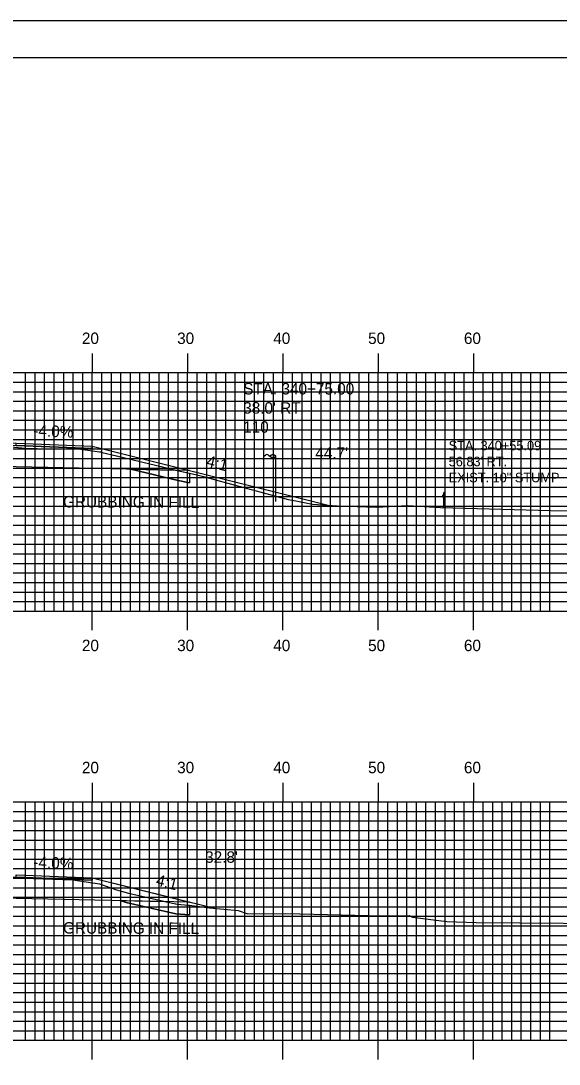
# Model space of a CAD drawing. Extents: x 1824360 to 1824703, y 442591 to 442811.
# Drawn here: x 1824537.8 to 1824594.3, y 442701.2 to 442810.5 of the extents above; entities that cross this region are included whole.
import ezdxf

# ---------------------------------------------------------------- set-up
doc = ezdxf.new("R2010")
doc.units = 0
for name, color, linetype in [('ANNOTATION', 7, 'Continuous'), ('BORDER', 7, 'Continuous'), ('D_Drainage_Text', 7, 'Continuous'), ('D_Roadway_Centerline', 7, 'Continuous'), ('D_Roadway_Edge_Shoulder', 7, 'Continuous'), ('D_Roadway_SlopeLines', 7, 'Continuous'), ('D_Roadway_SubGrade', 7, 'Continuous'), ('D_Text_Monospaced', 7, 'Continuous'), ('D_Text_Standard', 7, 'Continuous'), ('D_Utilities_Pole_Joint', 7, 'Continuous'), ('GRUBBING IN FILL', 7, 'Continuous'), ('H_V ANNOTATION', 7, 'Continuous'), ('MAJOR', 7, 'Continuous'), ('MINOR', 7, 'Continuous'), ('PLOT BOUNDARY', 7, 'Continuous'), ('S_Roadway_Centerline', 7, 'Continuous'), ('S_Trees_Dead_NonPay', 7, 'Continuous')]:
    doc.layers.add(name, color=color, linetype=linetype)

msp = doc.modelspace()

# ---------------------------------------------------------------- linework, layer by layer
at = {"layer": 'BORDER'}
msp.add_lwpolyline([(1824375.73, 442596.67), (1824695.73, 442596.67), (1824695.73, 442806.67), (1824375.73, 442806.67)], close=True, dxfattribs=at)
at = {"layer": 'D_Roadway_Centerline'}
msp.add_lwpolyline([(1824477.1, 442758.9), (1824495.16, 442763.42), (1824505.33, 442765.96), (1824513.33, 442766.28), (1824525.33, 442766.52), (1824537.33, 442766.28), (1824545.33, 442765.96), (1824555.51, 442763.42), (1824570.07, 442759.78)], dxfattribs=at)
at = {"layer": 'D_Roadway_Edge_Shoulder'}
for points in [[(1824537.33, 442766.28), (1824545.33, 442765.96), (1824545.33, 442765.71), (1824537.33, 442766.03)], [(1824537.33, 442721.03), (1824545.33, 442720.71), (1824545.33, 442720.46), (1824537.33, 442720.78)]]:
    msp.add_lwpolyline(points, close=True, dxfattribs=at)
at = {"layer": 'D_Roadway_SlopeLines'}
for points in [[(1824545.33, 442765.96), (1824555.51, 442763.42), (1824570.07, 442759.78)], [(1824545.33, 442720.71), (1824558.13, 442717.51)]]:
    msp.add_lwpolyline(points, dxfattribs=at)
at = {"layer": 'D_Roadway_SubGrade'}
for points in [[(1824513.33, 442763.78), (1824495.16, 442763.42), (1824505.33, 442765.96), (1824505.33, 442765.71), (1824513.33, 442766.03), (1824525.33, 442766.27), (1824537.33, 442766.03), (1824545.33, 442765.71), (1824545.33, 442765.96), (1824555.51, 442763.42), (1824537.33, 442763.78), (1824525.33, 442764.02)], [(1824513.33, 442718.53), (1824495.16, 442718.17), (1824505.33, 442720.71), (1824505.33, 442720.46), (1824513.33, 442720.78), (1824525.33, 442721.02), (1824537.33, 442720.78), (1824545.33, 442720.46), (1824545.33, 442720.71), (1824555.51, 442718.17), (1824537.33, 442718.53), (1824525.33, 442718.77)]]:
    msp.add_lwpolyline(points, close=True, dxfattribs=at)
at = {"layer": 'D_Utilities_Pole_Joint'}
for p, q in [((1824563.33, 442764.92), (1824563.49, 442765.03)), ((1824563.33, 442760.16), (1824563.33, 442764.92)), ((1824563.8, 442765.03), (1824563.96, 442764.92)), ((1824564.12, 442765.03), (1824563.96, 442764.92)), ((1824563.96, 442764.92), (1824564.12, 442764.8)), ((1824564.58, 442764.92), (1824564.43, 442765.03)), ((1824564.43, 442764.8), (1824564.58, 442764.92)), ((1824564.58, 442760.16), (1824564.58, 442764.92))]:
    msp.add_line(p, q, dxfattribs=at)
for centre, start, end in [((1824563.65, 442764.8), 90, 125.2644), ((1824563.65, 442764.8), 54.7356, 90), ((1824564.27, 442764.8), 90, 125.2644), ((1824564.27, 442765.03), 234.7356, 270), ((1824564.27, 442764.8), 54.7356, 90), ((1824564.27, 442765.03), 270, 305.2644)]:
    msp.add_arc(centre, 0.271, start, end, dxfattribs=at)
at = {"layer": 'GRUBBING IN FILL'}
for p, q in [((1824555.51, 442763.12), (1824555.51, 442762.1)), ((1824555.51, 442763.12), (1824555.51, 442762.1)), ((1824555.51, 442717.83), (1824555.51, 442716.83)), ((1824555.51, 442717.83), (1824555.51, 442716.83))]:
    msp.add_line(p, q, dxfattribs=at)
for points in [[(1824549.38, 442763.54), (1824554.35, 442762.35), (1824555.51, 442762.1)], [(1824549.38, 442763.54), (1824554.35, 442762.35), (1824555.51, 442762.1)], [(1824548.2, 442718.32), (1824548.87, 442718.13), (1824554.09, 442716.93), (1824555.51, 442716.83)], [(1824548.2, 442718.32), (1824548.87, 442718.13), (1824554.09, 442716.93), (1824555.51, 442716.83)]]:
    msp.add_lwpolyline(points, dxfattribs=at)
for points in [[(1824549.38, 442763.54), (1824554.06, 442763.45), (1824555.51, 442763.12), (1824555.51, 442762.1), (1824554.35, 442762.35), (1824551.86, 442762.95)], [(1824549.38, 442763.54), (1824554.06, 442763.45), (1824555.51, 442763.12), (1824555.51, 442762.1), (1824554.35, 442762.35), (1824551.86, 442762.95)], [(1824548.2, 442718.32), (1824552.95, 442718.22), (1824554.24, 442717.93), (1824555.01, 442717.87), (1824555.51, 442717.83), (1824555.51, 442716.83), (1824554.09, 442716.93), (1824551.48, 442717.53), (1824548.87, 442718.13)], [(1824548.2, 442718.32), (1824552.95, 442718.22), (1824554.24, 442717.93), (1824555.01, 442717.87), (1824555.51, 442717.83), (1824555.51, 442716.83), (1824554.09, 442716.93), (1824551.48, 442717.53), (1824548.87, 442718.13)]]:
    msp.add_lwpolyline(points, close=True, dxfattribs=at)
at = {"layer": 'MAJOR'}
for p, q in [((1824545.33, 442775.67), (1824545.33, 442773.67)), ((1824555.33, 442775.67), (1824555.33, 442773.67)), ((1824565.33, 442775.67), (1824565.33, 442773.67)), ((1824575.33, 442775.67), (1824575.33, 442773.67)), ((1824585.33, 442775.67), (1824585.33, 442773.67)), ((1824385.33, 442773.67), (1824665.33, 442773.67)), ((1824385.33, 442773.67), (1824665.33, 442773.67)), ((1824545.33, 442748.67), (1824545.33, 442773.67)), ((1824555.33, 442748.67), (1824555.33, 442773.67)), ((1824565.33, 442748.67), (1824565.33, 442773.67)), ((1824575.33, 442748.67), (1824575.33, 442773.67)), ((1824585.33, 442748.67), (1824585.33, 442773.67)), ((1824385.33, 442768.67), (1824665.33, 442768.67)), ((1824385.33, 442763.67), (1824665.33, 442763.67)), ((1824385.33, 442758.67), (1824665.33, 442758.67)), ((1824385.33, 442753.67), (1824665.33, 442753.67)), ((1824385.33, 442748.67), (1824665.33, 442748.67)), ((1824385.33, 442748.67), (1824665.33, 442748.67)), ((1824545.33, 442746.66), (1824545.33, 442748.67)), ((1824555.33, 442746.66), (1824555.33, 442748.67)), ((1824565.33, 442746.66), (1824565.33, 442748.67)), ((1824575.33, 442746.66), (1824575.33, 442748.67)), ((1824585.33, 442746.66), (1824585.33, 442748.67)), ((1824545.33, 442730.67), (1824545.33, 442728.67)), ((1824555.33, 442730.67), (1824555.33, 442728.67)), ((1824565.33, 442730.67), (1824565.33, 442728.67)), ((1824575.33, 442730.67), (1824575.33, 442728.67)), ((1824585.33, 442730.67), (1824585.33, 442728.67)), ((1824385.33, 442728.67), (1824665.33, 442728.67)), ((1824385.33, 442728.67), (1824665.33, 442728.67)), ((1824545.33, 442703.67), (1824545.33, 442728.67)), ((1824555.33, 442703.67), (1824555.33, 442728.67)), ((1824565.33, 442703.67), (1824565.33, 442728.67)), ((1824575.33, 442703.67), (1824575.33, 442728.67)), ((1824585.33, 442703.67), (1824585.33, 442728.67)), ((1824385.33, 442723.67), (1824665.33, 442723.67)), ((1824385.33, 442718.67), (1824665.33, 442718.67)), ((1824385.33, 442713.67), (1824665.33, 442713.67)), ((1824385.33, 442708.67), (1824665.33, 442708.67)), ((1824385.33, 442703.67), (1824665.33, 442703.67)), ((1824385.33, 442703.67), (1824665.33, 442703.67)), ((1824545.33, 442701.66), (1824545.33, 442703.67)), ((1824555.33, 442701.66), (1824555.33, 442703.67)), ((1824565.33, 442701.66), (1824565.33, 442703.67)), ((1824575.33, 442701.66), (1824575.33, 442703.67)), ((1824585.33, 442701.66), (1824585.33, 442703.67))]:
    msp.add_line(p, q, dxfattribs=at)
at = {"layer": 'MINOR'}
for p, q in [((1824538.33, 442748.67), (1824538.33, 442773.67)), ((1824539.33, 442748.67), (1824539.33, 442773.67)), ((1824540.33, 442748.67), (1824540.33, 442773.67)), ((1824541.33, 442748.67), (1824541.33, 442773.67)), ((1824542.33, 442748.67), (1824542.33, 442773.67)), ((1824543.33, 442748.67), (1824543.33, 442773.67)), ((1824544.33, 442748.67), (1824544.33, 442773.67)), ((1824546.33, 442748.67), (1824546.33, 442773.67)), ((1824547.33, 442748.67), (1824547.33, 442773.67)), ((1824548.33, 442748.67), (1824548.33, 442773.67)), ((1824549.33, 442748.67), (1824549.33, 442773.67)), ((1824550.33, 442748.67), (1824550.33, 442773.67)), ((1824551.33, 442748.67), (1824551.33, 442773.67)), ((1824552.33, 442748.67), (1824552.33, 442773.67)), ((1824553.33, 442748.67), (1824553.33, 442773.67)), ((1824554.33, 442748.67), (1824554.33, 442773.67)), ((1824556.33, 442748.67), (1824556.33, 442773.67)), ((1824557.33, 442748.67), (1824557.33, 442773.67)), ((1824558.33, 442748.67), (1824558.33, 442773.67)), ((1824559.33, 442748.67), (1824559.33, 442773.67)), ((1824560.33, 442748.67), (1824560.33, 442773.67)), ((1824561.33, 442748.67), (1824561.33, 442773.67)), ((1824562.33, 442748.67), (1824562.33, 442773.67)), ((1824563.33, 442748.67), (1824563.33, 442773.67)), ((1824564.33, 442748.67), (1824564.33, 442773.67)), ((1824566.33, 442748.67), (1824566.33, 442773.67)), ((1824567.33, 442748.67), (1824567.33, 442773.67)), ((1824568.33, 442748.67), (1824568.33, 442773.67)), ((1824569.33, 442748.67), (1824569.33, 442773.67)), ((1824570.33, 442748.67), (1824570.33, 442773.67)), ((1824571.33, 442748.67), (1824571.33, 442773.67)), ((1824572.33, 442748.67), (1824572.33, 442773.67)), ((1824573.33, 442748.67), (1824573.33, 442773.67)), ((1824574.33, 442748.67), (1824574.33, 442773.67)), ((1824576.33, 442748.67), (1824576.33, 442773.67)), ((1824577.33, 442748.67), (1824577.33, 442773.67)), ((1824578.33, 442748.67), (1824578.33, 442773.67)), ((1824579.33, 442748.67), (1824579.33, 442773.67)), ((1824580.33, 442748.67), (1824580.33, 442773.67)), ((1824581.33, 442748.67), (1824581.33, 442773.67)), ((1824582.33, 442748.67), (1824582.33, 442773.67)), ((1824583.33, 442748.67), (1824583.33, 442773.67)), ((1824584.33, 442748.67), (1824584.33, 442773.67)), ((1824586.33, 442748.67), (1824586.33, 442773.67)), ((1824587.33, 442748.67), (1824587.33, 442773.67)), ((1824588.33, 442748.67), (1824588.33, 442773.67)), ((1824589.33, 442748.67), (1824589.33, 442773.67)), ((1824590.33, 442748.67), (1824590.33, 442773.67)), ((1824591.33, 442748.67), (1824591.33, 442773.67)), ((1824592.33, 442748.67), (1824592.33, 442773.67)), ((1824593.33, 442748.67), (1824593.33, 442773.67)), ((1824385.33, 442772.67), (1824665.33, 442772.67)), ((1824385.33, 442771.67), (1824665.33, 442771.67)), ((1824385.33, 442770.67), (1824665.33, 442770.67)), ((1824385.33, 442769.67), (1824665.33, 442769.67)), ((1824385.33, 442767.67), (1824665.33, 442767.67)), ((1824385.33, 442766.67), (1824665.33, 442766.67)), ((1824385.33, 442765.67), (1824665.33, 442765.67)), ((1824385.33, 442764.67), (1824665.33, 442764.67)), ((1824385.33, 442762.67), (1824665.33, 442762.67)), ((1824385.33, 442761.67), (1824665.33, 442761.67)), ((1824385.33, 442760.67), (1824665.33, 442760.67)), ((1824385.33, 442759.67), (1824665.33, 442759.67)), ((1824385.33, 442757.67), (1824665.33, 442757.67)), ((1824385.33, 442756.67), (1824665.33, 442756.67)), ((1824385.33, 442755.67), (1824665.33, 442755.67)), ((1824385.33, 442754.67), (1824665.33, 442754.67)), ((1824385.33, 442752.67), (1824665.33, 442752.67)), ((1824385.33, 442751.67), (1824665.33, 442751.67)), ((1824385.33, 442750.67), (1824665.33, 442750.67)), ((1824385.33, 442749.67), (1824665.33, 442749.67)), ((1824538.33, 442703.67), (1824538.33, 442728.67)), ((1824539.33, 442703.67), (1824539.33, 442728.67)), ((1824540.33, 442703.67), (1824540.33, 442728.67)), ((1824541.33, 442703.67), (1824541.33, 442728.67)), ((1824542.33, 442703.67), (1824542.33, 442728.67)), ((1824543.33, 442703.67), (1824543.33, 442728.67)), ((1824544.33, 442703.67), (1824544.33, 442728.67)), ((1824546.33, 442703.67), (1824546.33, 442728.67)), ((1824547.33, 442703.67), (1824547.33, 442728.67)), ((1824548.33, 442703.67), (1824548.33, 442728.67)), ((1824549.33, 442703.67), (1824549.33, 442728.67)), ((1824550.33, 442703.67), (1824550.33, 442728.67)), ((1824551.33, 442703.67), (1824551.33, 442728.67)), ((1824552.33, 442703.67), (1824552.33, 442728.67)), ((1824553.33, 442703.67), (1824553.33, 442728.67)), ((1824554.33, 442703.67), (1824554.33, 442728.67)), ((1824556.33, 442703.67), (1824556.33, 442728.67)), ((1824557.33, 442703.67), (1824557.33, 442728.67)), ((1824558.33, 442703.67), (1824558.33, 442728.67)), ((1824559.33, 442703.67), (1824559.33, 442728.67)), ((1824560.33, 442703.67), (1824560.33, 442728.67)), ((1824561.33, 442703.67), (1824561.33, 442728.67)), ((1824562.33, 442703.67), (1824562.33, 442728.67)), ((1824563.33, 442703.67), (1824563.33, 442728.67)), ((1824564.33, 442703.67), (1824564.33, 442728.67)), ((1824566.33, 442703.67), (1824566.33, 442728.67)), ((1824567.33, 442703.67), (1824567.33, 442728.67)), ((1824568.33, 442703.67), (1824568.33, 442728.67)), ((1824569.33, 442703.67), (1824569.33, 442728.67)), ((1824570.33, 442703.67), (1824570.33, 442728.67)), ((1824571.33, 442703.67), (1824571.33, 442728.67)), ((1824572.33, 442703.67), (1824572.33, 442728.67)), ((1824573.33, 442703.67), (1824573.33, 442728.67)), ((1824574.33, 442703.67), (1824574.33, 442728.67)), ((1824576.33, 442703.67), (1824576.33, 442728.67)), ((1824577.33, 442703.67), (1824577.33, 442728.67)), ((1824578.33, 442703.67), (1824578.33, 442728.67)), ((1824579.33, 442703.67), (1824579.33, 442728.67)), ((1824580.33, 442703.67), (1824580.33, 442728.67)), ((1824581.33, 442703.67), (1824581.33, 442728.67)), ((1824582.33, 442703.67), (1824582.33, 442728.67)), ((1824583.33, 442703.67), (1824583.33, 442728.67)), ((1824584.33, 442703.67), (1824584.33, 442728.67)), ((1824586.33, 442703.67), (1824586.33, 442728.67)), ((1824587.33, 442703.67), (1824587.33, 442728.67)), ((1824588.33, 442703.67), (1824588.33, 442728.67)), ((1824589.33, 442703.67), (1824589.33, 442728.67)), ((1824590.33, 442703.67), (1824590.33, 442728.67)), ((1824591.33, 442703.67), (1824591.33, 442728.67)), ((1824592.33, 442703.67), (1824592.33, 442728.67)), ((1824593.33, 442703.67), (1824593.33, 442728.67)), ((1824385.33, 442727.67), (1824665.33, 442727.67)), ((1824385.33, 442726.67), (1824665.33, 442726.67)), ((1824385.33, 442725.67), (1824665.33, 442725.67)), ((1824385.33, 442724.67), (1824665.33, 442724.67)), ((1824385.33, 442722.67), (1824665.33, 442722.67)), ((1824385.33, 442721.67), (1824665.33, 442721.67)), ((1824385.33, 442720.67), (1824665.33, 442720.67)), ((1824385.33, 442719.67), (1824665.33, 442719.67)), ((1824385.33, 442717.67), (1824665.33, 442717.67)), ((1824385.33, 442716.67), (1824665.33, 442716.67)), ((1824385.33, 442715.67), (1824665.33, 442715.67)), ((1824385.33, 442714.67), (1824665.33, 442714.67)), ((1824385.33, 442712.67), (1824665.33, 442712.67)), ((1824385.33, 442711.67), (1824665.33, 442711.67)), ((1824385.33, 442710.67), (1824665.33, 442710.67)), ((1824385.33, 442709.67), (1824665.33, 442709.67)), ((1824385.33, 442707.67), (1824665.33, 442707.67)), ((1824385.33, 442706.67), (1824665.33, 442706.67)), ((1824385.33, 442705.67), (1824665.33, 442705.67)), ((1824385.33, 442704.67), (1824665.33, 442704.67))]:
    msp.add_line(p, q, dxfattribs=at)
at = {"layer": 'PLOT BOUNDARY'}
msp.add_lwpolyline([(1824359.55, 442590.55), (1824699.55, 442590.55), (1824699.55, 442810.55), (1824359.55, 442810.55)], close=True, dxfattribs=at)
at = {"layer": 'S_Roadway_Centerline'}
for points in [[(1824536.78, 442765.9), (1824538.33, 442765.75), (1824540.82, 442765.68), (1824544.12, 442765.64), (1824546.08, 442765.37), (1824546.27, 442765.36), (1824546.37, 442765.29), (1824547.88, 442764.93), (1824554.57, 442763.33), (1824556.29, 442762.95), (1824556.99, 442762.78), (1824558.65, 442762.33), (1824565.88, 442760.36), (1824566.67, 442760.23), (1824568.43, 442759.88), (1824571.05, 442759.72), (1824575.15, 442759.58), (1824578.44, 442759.74), (1824581.86, 442759.52), (1824593.41, 442759.22), (1824617.91, 442758.72)], [(1824536.07, 442720.75), (1824543.24, 442720.49), (1824543.26, 442720.49), (1824543.29, 442720.48), (1824546.1, 442720.08), (1824547.88, 442719.44), (1824549.11, 442719.1), (1824554.24, 442717.93), (1824555.78, 442717.81), (1824557.62, 442717.56), (1824560.62, 442717.27), (1824561.65, 442716.93), (1824565.62, 442716.96), (1824568.56, 442716.89), (1824575.75, 442716.71), (1824578.58, 442716.74), (1824578.92, 442716.58), (1824582.51, 442716.11), (1824585.61, 442716.03), (1824599.32, 442715.92)]]:
    msp.add_lwpolyline(points, dxfattribs=at)
at = {"layer": 'S_Trees_Dead_NonPay'}
for p, q in [((1824582.11, 442760.75), (1824582.09, 442760.86)), ((1824582.13, 442760.7), (1824582.16, 442760.59)), ((1824582.16, 442760.68), (1824582.2, 442760.67)), ((1824582.22, 442759.99), (1824582.16, 442760.02)), ((1824582.2, 442760.93), (1824582.2, 442760.8)), ((1824582.2, 442760.74), (1824582.2, 442760.57)), ((1824582.2, 442760.36), (1824582.2, 442760.17)), ((1824582.22, 442760.08), (1824582.22, 442759.83)), ((1824582.25, 442760.89), (1824582.29, 442760.89)), ((1824582.25, 442760.52), (1824582.25, 442760.3)), ((1824582.29, 442760.98), (1824582.29, 442760.85)), ((1824582.29, 442760.7), (1824582.29, 442760.37)), ((1824582.29, 442760.51), (1824582.34, 442760.53)), ((1824582.3, 442760.77), (1824582.34, 442760.77)), ((1824582.31, 442760.16), (1824582.31, 442759.98)), ((1824582.34, 442759.83), (1824582.34, 442761.09)), ((1824582.21, 442759.73), (1824582.19, 442759.64)), ((1824582.26, 442759.86), (1824582.26, 442759.74))]:
    msp.add_line(p, q, dxfattribs=at)
for points in [[(1824582.16, 442760.55), (1824582.11, 442760.75), (1824582.04, 442760.76)], [(1824582.16, 442761.05), (1824582.16, 442759.82), (1824582.14, 442759.64), (1824582.1, 442759.55), (1824582.16, 442759.53), (1824582.11, 442759.51), (1824582.27, 442759.52), (1824582.29, 442759.59)], [(1824582.23, 442760.14), (1824582.26, 442760.13), (1824582.28, 442760.15)], [(1824582.27, 442759.55), (1824582.38, 442759.51), (1824582.4, 442759.55), (1824582.36, 442759.58), (1824582.34, 442759.83)]]:
    msp.add_lwpolyline(points, dxfattribs=at)
for centre, radius, start, end in [((1824582.21, 442761.01), 0.0616, 111.5712, 133.6807), ((1824582.17, 442761.04), 0.0147, 133.6807, 153.5407), ((1824582.16, 442761.05), 0.0037, 153.5407, 193.6807), ((1824582.16, 442761.05), 0.0037, 193.6807, 233.8207), ((1824582.17, 442761.06), 0.0147, 233.8207, 253.6807), ((1824582.18, 442761.1), 0.0616, 253.6807, 275.7902), ((1824582.36, 442760.62), 0.478, 103.6807, 111.5712), ((1824582.14, 442761.52), 0.478, 275.7902, 283.6807), ((1824582.36, 442760.62), 0.478, 95.7902, 103.6807), ((1824582.14, 442761.52), 0.478, 283.6807, 291.5712), ((1824582.32, 442761.04), 0.0616, 73.6807, 95.7902), ((1824582.3, 442761.13), 0.0616, 291.5712, 313.6807), ((1824582.34, 442761.09), 0.0037, 13.6807, 53.8207), ((1824582.33, 442761.08), 0.0147, 53.8207, 73.6807), ((1824582.33, 442761.09), 0.0147, 313.6807, 333.5407), ((1824582.34, 442761.09), 0.0037, 333.5407, 13.6807)]:
    msp.add_arc(centre, radius, start, end, dxfattribs=at)

# ---------------------------------------------------------------- texts
at = {"layer": 'ANNOTATION'}
for s, rotation, p in [('-4.0%', 357.7094, (1824539.13, 442767.01)), ('4:1', 345.9638, (1824557.21, 442763.86)), ('-4.0%', 357.7094, (1824539.13, 442721.76)), ('4:1', 345.9638, (1824551.93, 442719.93))]:
    msp.add_text(s, height=1.2, rotation=rotation, dxfattribs=at).set_placement(p)
at = {"layer": 'D_Drainage_Text'}
for s, p in [('STA. 340+75.00', (1824561.16, 442771.38)), ("38.0' RT", (1824561.16, 442769.37)), ('110', (1824561.16, 442767.37))]:
    msp.add_text(s, height=1.2, dxfattribs=at).set_placement(p)
at = {"layer": 'D_Text_Monospaced'}
for s, p in [('STA. 340+55.09', (1824582.71, 442765.52)), ("56.83' RT.", (1824582.71, 442763.85)), ('EXIST. 10" STUMP', (1824582.71, 442762.17))]:
    msp.add_text(s, height=1, dxfattribs=at).set_placement(p)
at = {"layer": 'D_Text_Standard'}
for s, p in [("44.7'", (1824568.72, 442764.63)), ("32.8'", (1824557.17, 442722.28))]:
    msp.add_text(s, height=1.2, dxfattribs=at).set_placement(p)
at = {"layer": 'GRUBBING IN FILL'}
for p in [(1824542.26, 442759.54), (1824542.26, 442714.86)]:
    msp.add_text('GRUBBING IN FILL', height=1.2, rotation=359.8053, dxfattribs=at).set_placement(p)
at = {"layer": 'H_V ANNOTATION'}
for s, p in [('20', (1824544.24, 442776.67)), ('30', (1824554.23, 442776.67)), ('40', (1824564.31, 442776.67)), ('50', (1824574.26, 442776.67)), ('60', (1824584.31, 442776.67)), ('20', (1824544.24, 442744.47)), ('30', (1824554.23, 442744.47)), ('40', (1824564.31, 442744.47)), ('50', (1824574.26, 442744.47)), ('60', (1824584.31, 442744.47)), ('20', (1824544.24, 442731.67)), ('30', (1824554.23, 442731.67)), ('40', (1824564.31, 442731.67)), ('50', (1824574.26, 442731.67)), ('60', (1824584.31, 442731.67))]:
    msp.add_text(s, height=1.2, dxfattribs=at).set_placement(p)

doc.saveas('drawing.dxf')
